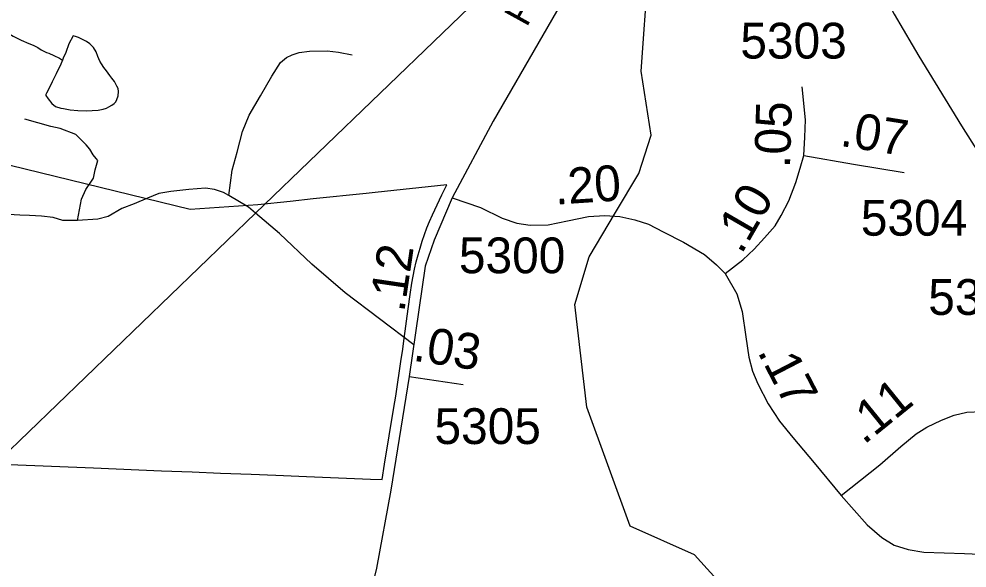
# Model space of a CAD drawing. Extents: x 2001466 to 2224147, y 644118 to 847247.
# Drawn here: x 2065678 to 2068990, y 660052 to 661970 of the extents above; entities that cross this region are included whole.
import ezdxf

# ---------------------------------------------------------------- set-up
doc = ezdxf.new("R2010")
doc.units = 0
for name, color, linetype in [('Exist Boundary Political City Limit New', 7, 'Continuous'), ('Exist Hydrographic Creek Single Shore', 7, 'Continuous'), ('Exist Hydrographic Misc Water Feature', 7, 'Continuous'), ('Exist Road Non-System Type 51', 7, 'Continuous'), ('Exist Road Secondary Mileage Hundredths English Label', 7, 'Continuous'), ('Exist Road Secondary Type 51 Attributed', 7, 'Continuous'), ('Exist Road Secondary Type 51 Label', 7, 'Continuous'), ('Exist Road Secondary Type 51 Number Label', 7, 'Continuous'), ('Exist Utilities Electrical Transmission Line', 7, 'Continuous'), ('Map Preparation Boundary City Limit Buffer Line', 7, 'Continuous')]:
    doc.layers.add(name, color=color, linetype=linetype)

msp = doc.modelspace()

# ---------------------------------------------------------------- linework, layer by layer
at = {"layer": 'Exist Boundary Political City Limit New'}
msp.add_lwpolyline([(2064939.2, 660441.6), (2065938.4, 660401.7), (2066017.4, 660398.6), (2066096.2, 660395.4), (2066175.2, 660392.2), (2066283, 660387.9), (2066381.5, 660384), (2066489.4, 660379.7), (2066574.5, 660376.3), (2066682.1, 660372), (2066905.5, 660363.1), (2066946.2, 660361.4), (2066955.2, 660415.5), (2066971.5, 660514.1), (2066987.4, 660612.7), (2066993.9, 660653.1), (2067013.4, 660781.6), (2067017.4, 660809.2), (2067023.4, 660853.9), (2067036.9, 660957.8), (2067044, 661008.2), (2067050.4, 661047.1), (2067054.9, 661072), (2067059.9, 661096.8), (2067065.6, 661121.4), (2067072, 661145.9), (2067079, 661170.2), (2067086.4, 661193.8), (2067094.4, 661217.2), (2067103, 661240.3), (2067112.2, 661263.2), (2067122.1, 661285.9), (2067138.4, 661321.1), (2067155.2, 661356.2), (2067172.6, 661390.9), (2066921.9, 661364.4), (2066890.2, 661361.1), (2066705, 661341.6), (2066625, 661333.2), (2066511.9, 661321.4), (2066275.4, 661305), (2065593.8, 661470.8)], dxfattribs=at)
at = {"layer": 'Exist Hydrographic Creek Single Shore'}
for points in [[(2067762.3, 661294), (2067844, 661431.1), (2067886.1, 661564.8), (2067852, 661788.5), (2067876, 662129.2), (2067934.1, 662305.2)], [(2068744.1, 658173.9), (2068740.9, 658223.9), (2068766, 658384.2), (2068714.9, 658798.6), (2068540, 659225.3), (2068298, 659414), (2068188.9, 659704.9), (2068137.9, 659988.1), (2068038, 660098.4), (2067813.1, 660198.1), (2067662, 660614.6), (2067619.9, 660973), (2067670, 661139.3), (2067762.3, 661294)]]:
    msp.add_lwpolyline(points, dxfattribs=at)
at = {"layer": 'Exist Hydrographic Misc Water Feature'}
msp.add_line((2068799, 661879.8), (2068821.9, 661840.5), dxfattribs=at)
for points in [[(2068684.1, 662086.3), (2068736, 661987.7), (2068799, 661879.8)], [(2068684.1, 662086.3), (2068736, 661987.7), (2068799, 661879.8)], [(2065475.5, 661954.3), (2065485.9, 661955.6), (2065491.5, 661956.4), (2065507.5, 661958.4), (2065521.4, 661956.4), (2065533.5, 661954.4), (2065547.5, 661952.5), (2065567.4, 661946.5), (2065585.4, 661940.6), (2065601.4, 661934.6), (2065625.4, 661926.6), (2065639.5, 661920.6), (2065657.4, 661910.7), (2065685.5, 661896.7), (2065711.5, 661884.8), (2065727.5, 661878.8), (2065743.5, 661870.9), (2065755.6, 661862.9), (2065773.6, 661852.9), (2065781.6, 661850.9), (2065799.5, 661842.9), (2065819.6, 661833), (2065829.6, 661827)], [(2065829.6, 661827), (2065823.5, 661813), (2065807.7, 661779), (2065793.7, 661751), (2065783.7, 661731), (2065773.8, 661710.9), (2065771.8, 661706.9), (2065771.8, 661702.9), (2065779.8, 661690.9), (2065791.9, 661675), (2065805.8, 661665), (2065823.9, 661659.1), (2065833.7, 661657.1), (2065855.9, 661653.1), (2065883.7, 661651.1), (2065911.8, 661649.2), (2065933.8, 661651.2), (2065953.9, 661651.3), (2065971.7, 661655.3), (2065983.8, 661659.3), (2065991.8, 661663.4), (2066001.9, 661669.4), (2066009.9, 661675.4), (2066015.8, 661681.4), (2066019.9, 661689.4), (2066023.6, 661701.4), (2066025.6, 661717.4), (2066023.6, 661727.4), (2066019.7, 661735.4), (2066011.7, 661751.4), (2066001.7, 661763.4), (2065995.5, 661773.3), (2065983.6, 661789.3), (2065973.6, 661801.3), (2065965.6, 661813.2), (2065959.6, 661823.2), (2065953.5, 661839.3), (2065947.5, 661855.3), (2065937.5, 661871.2), (2065925.4, 661883.2), (2065913.5, 661891.2), (2065899.5, 661899.2), (2065885.4, 661905.2), (2065875.3, 661909), (2065867.3, 661911), (2065851.3, 661883.1), (2065841.5, 661853.1), (2065831.5, 661833), (2065829.6, 661827)], [(2068821.9, 661840.5), (2068971, 661597.4), (2069029.2, 661504.5)], [(2068821.9, 661840.5), (2068971, 661597.4), (2069029.2, 661504.5)]]:
    msp.add_lwpolyline(points, dxfattribs=at)
at = {"layer": 'Exist Road Non-System Type 51'}
for points in [[(2066410.3, 661354.1), (2066422.1, 661441.9), (2066439.4, 661505.5), (2066458.8, 661577.1), (2066482, 661634.7), (2066521.4, 661701.9), (2066560.8, 661771.1), (2066591.8, 661818.4), (2066612.1, 661836), (2066632.3, 661845.6), (2066656.5, 661853.1), (2066692.6, 661858.4), (2066754.6, 661859.1), (2066794.5, 661854.3), (2066842.3, 661845.3)], [(2065882.5, 661266.8), (2065896, 661340.6), (2065910.7, 661374.3), (2065937.5, 661413.7), (2065944.1, 661443.6), (2065948.5, 661459.5), (2065952.8, 661475.4), (2065946.9, 661483.5), (2065937.2, 661495.7), (2065925.6, 661516), (2065911.9, 661530.2), (2065876.6, 661566.9), (2065821.1, 661588.1), (2065789.2, 661594.7), (2065697.7, 661620.6)], [(2066410.3, 661354.1), (2066392.5, 661364.5), (2066360.7, 661375.1), (2066328.8, 661379.8), (2066270.7, 661374.9), (2066208.6, 661368.2), (2066166.5, 661361.1), (2066126.1, 661343.9), (2066079.7, 661324.8), (2066037.4, 661307.7), (2065988.8, 661280.7), (2065952.6, 661271.4), (2065882.5, 661266.8)], [(2066503.8, 661292), (2066479.5, 661312.7), (2066410.3, 661354.1)], [(2065882.5, 661266.8), (2065830.5, 661265.9), (2065796.7, 661276.6), (2065756.8, 661281.4), (2065714.9, 661284.2), (2065680.9, 661284.9), (2065641, 661287.7), (2065584.5, 661266.9), (2065540.1, 661247.8), (2065517.7, 661226.2), (2065478.9, 661185), (2065450.2, 661153.6), (2065421.4, 661112.2), (2065355.9, 661041.5)], [(2067056.8, 660831.4), (2066817.4, 661013.8), (2066701.4, 661114.2), (2066587.6, 661220.5), (2066503.8, 661292)]]:
    msp.add_lwpolyline(points, dxfattribs=at)
at = {"layer": 'Exist Road Secondary Type 51 Attributed'}
for points in [[(2068025, 662822.7), (2067907.9, 662614.6), (2067682, 662215.4), (2067334.7, 661613.3), (2067191.5, 661345)], [(2068420.2, 661493.1), (2068424, 661557.3), (2068425.9, 661617.7), (2068414.6, 661732.8)], [(2068144.9, 661081.7), (2068207.1, 661128.9), (2068246.7, 661166.6), (2068282.5, 661206.3), (2068320.3, 661247.8), (2068341, 661283.7), (2068367.4, 661334.6), (2068391.9, 661398.8), (2068407, 661449.7), (2068420.2, 661493.1)], [(2068420.2, 661493.1), (2068593.7, 661462.9), (2068771, 661434.6)], [(2067191.5, 661345), (2067127.8, 661197.1), (2067097.2, 661106.3), (2067040.6, 660721.7)], [(2067191.5, 661345), (2067290.5, 661312), (2067365.9, 661274.2), (2067416.8, 661257.2), (2067464, 661249.7), (2067526.2, 661251.6), (2067594.1, 661264.8), (2067667.7, 661279.9), (2067724.3, 661283.7), (2067777.1, 661279.9), (2067829.9, 661268.6), (2067877, 661253.5), (2067928, 661227), (2067999.6, 661191.2), (2068073.2, 661147.8), (2068114.7, 661111.9), (2068144.9, 661081.7)], [(2068144.9, 661081.7), (2068186.2, 661010.6), (2068204.4, 660948.1), (2068217.4, 660859.7), (2068227.8, 660789.4), (2068240.8, 660740), (2068259, 660695.7), (2068295.4, 660625.5), (2068334.4, 660565.7), (2068381.2, 660508.4), (2068456.6, 660420), (2068550.2, 660305.5)], [(2067040.6, 660721.7), (2066976.9, 660324.6), (2066927.3, 660052.1), (2066840.7, 659699.3), (2066737.3, 659350.7), (2066525.1, 658605), (2066413.2, 658199.3), (2066338.8, 657914.1), (2066307.1, 657715.6), (2066271.2, 657434.6), (2066250.6, 657247.6), (2066251.7, 657100.8), (2066285, 656860), (2066324, 656662.4), (2066462.8, 656292.7), (2066553.6, 656089.9), (2066584.7, 656000.2), (2066591.1, 655937.8), (2066585.8, 655767.8), (2066563.6, 655617)], [(2067040.6, 660721.7), (2067230.2, 660693.1)], [(2068550.2, 660305.5), (2068685.5, 660412.2), (2068758.3, 660477.2), (2068812.9, 660521.4), (2068849.3, 660544.8), (2068901.3, 660568.3), (2068945.5, 660586.5), (2068989.7, 660596.9), (2069041.7, 660599.5)], [(2068550.2, 660305.5), (2068641.2, 660202.6), (2068692, 660158.5), (2068736.1, 660132), (2068784.7, 660116.5), (2068839.8, 660107.7), (2068981.1, 660103.3), (2069221.6, 660092.2)]]:
    msp.add_lwpolyline(points, dxfattribs=at)
at = {"layer": 'Exist Utilities Electrical Transmission Line'}
for points in [[(2067536.5, 662659.6), (2067524, 662467.9), (2067374.7, 662131.5), (2066503.8, 661292)], [(2066503.8, 661292), (2063433.4, 658332.1), (2063369.4, 658270.5)]]:
    msp.add_lwpolyline(points, dxfattribs=at)
at = {"layer": 'Map Preparation Boundary City Limit Buffer Line'}
msp.add_lwpolyline([(2064939.2, 660441.6), (2065938.4, 660401.7), (2066017.4, 660398.6), (2066096.2, 660395.4), (2066175.2, 660392.2), (2066283, 660387.9), (2066381.5, 660384), (2066489.4, 660379.7), (2066574.5, 660376.3), (2066682.1, 660372), (2066905.5, 660363.1), (2066946.2, 660361.4), (2066955.2, 660415.5), (2066971.5, 660514.1), (2066987.4, 660612.7), (2066993.9, 660653.1), (2067013.4, 660781.6), (2067017.4, 660809.2), (2067023.4, 660853.9), (2067036.9, 660957.8), (2067044, 661008.2), (2067050.4, 661047.1), (2067054.9, 661072), (2067059.9, 661096.8), (2067065.6, 661121.4), (2067072, 661145.9), (2067079, 661170.2), (2067086.4, 661193.8), (2067094.4, 661217.2), (2067103, 661240.3), (2067112.2, 661263.2), (2067122.1, 661285.9), (2067138.4, 661321.1), (2067155.2, 661356.2), (2067172.6, 661390.9), (2066921.9, 661364.4), (2066890.2, 661361.1), (2066705, 661341.6), (2066625, 661333.2), (2066511.9, 661321.4), (2066275.4, 661305), (2065593.8, 661470.8)], dxfattribs=at)

# ---------------------------------------------------------------- texts
at = {"layer": 'Exist Road Secondary Mileage Hundredths English Label'}
for s, rotation, p in [('.05', 88.2108, (2068371.4, 661448.5)), ('.07', 350.928, (2068543.4, 661527.5)), ('.20', 3.8157, (2067552.4, 661321.5)), ('.10', 59.947, (2068201.8, 661145)), ('.12', 81.6334, (2067023.5, 660943.2)), ('.03', 351.4256, (2067051.2, 660777)), ('.17', 297.393, (2068256.3, 660808.1)), ('.11', 39.0084, (2068629.5, 660480.7))]:
    msp.add_text(s, height=125, rotation=rotation, dxfattribs=at).set_placement(p)
at = {"layer": 'Exist Road Secondary Type 51 Label'}
msp.add_text('Rd.', height=95, rotation=61.0873, dxfattribs=at).set_placement((2067451.7, 661939.3))
at = {"layer": 'Exist Road Secondary Type 51 Number Label'}
for s, p in [('5303', (2068198.2, 661832.1)), ('5304', (2068619.1, 661213.3)), ('5300', (2067214.8, 661082)), ('5302', (2068854.6, 660936.5)), ('5305', (2067129.4, 660485.4))]:
    msp.add_text(s, height=125, dxfattribs=at).set_placement(p)

doc.saveas('drawing.dxf')
